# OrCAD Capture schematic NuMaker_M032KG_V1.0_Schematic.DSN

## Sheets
1 Nu-Link2-Me: size A3; title: Nu-Link2-Me; rev: 1.0; company: CMHuang; note: Nu-Link2-Me
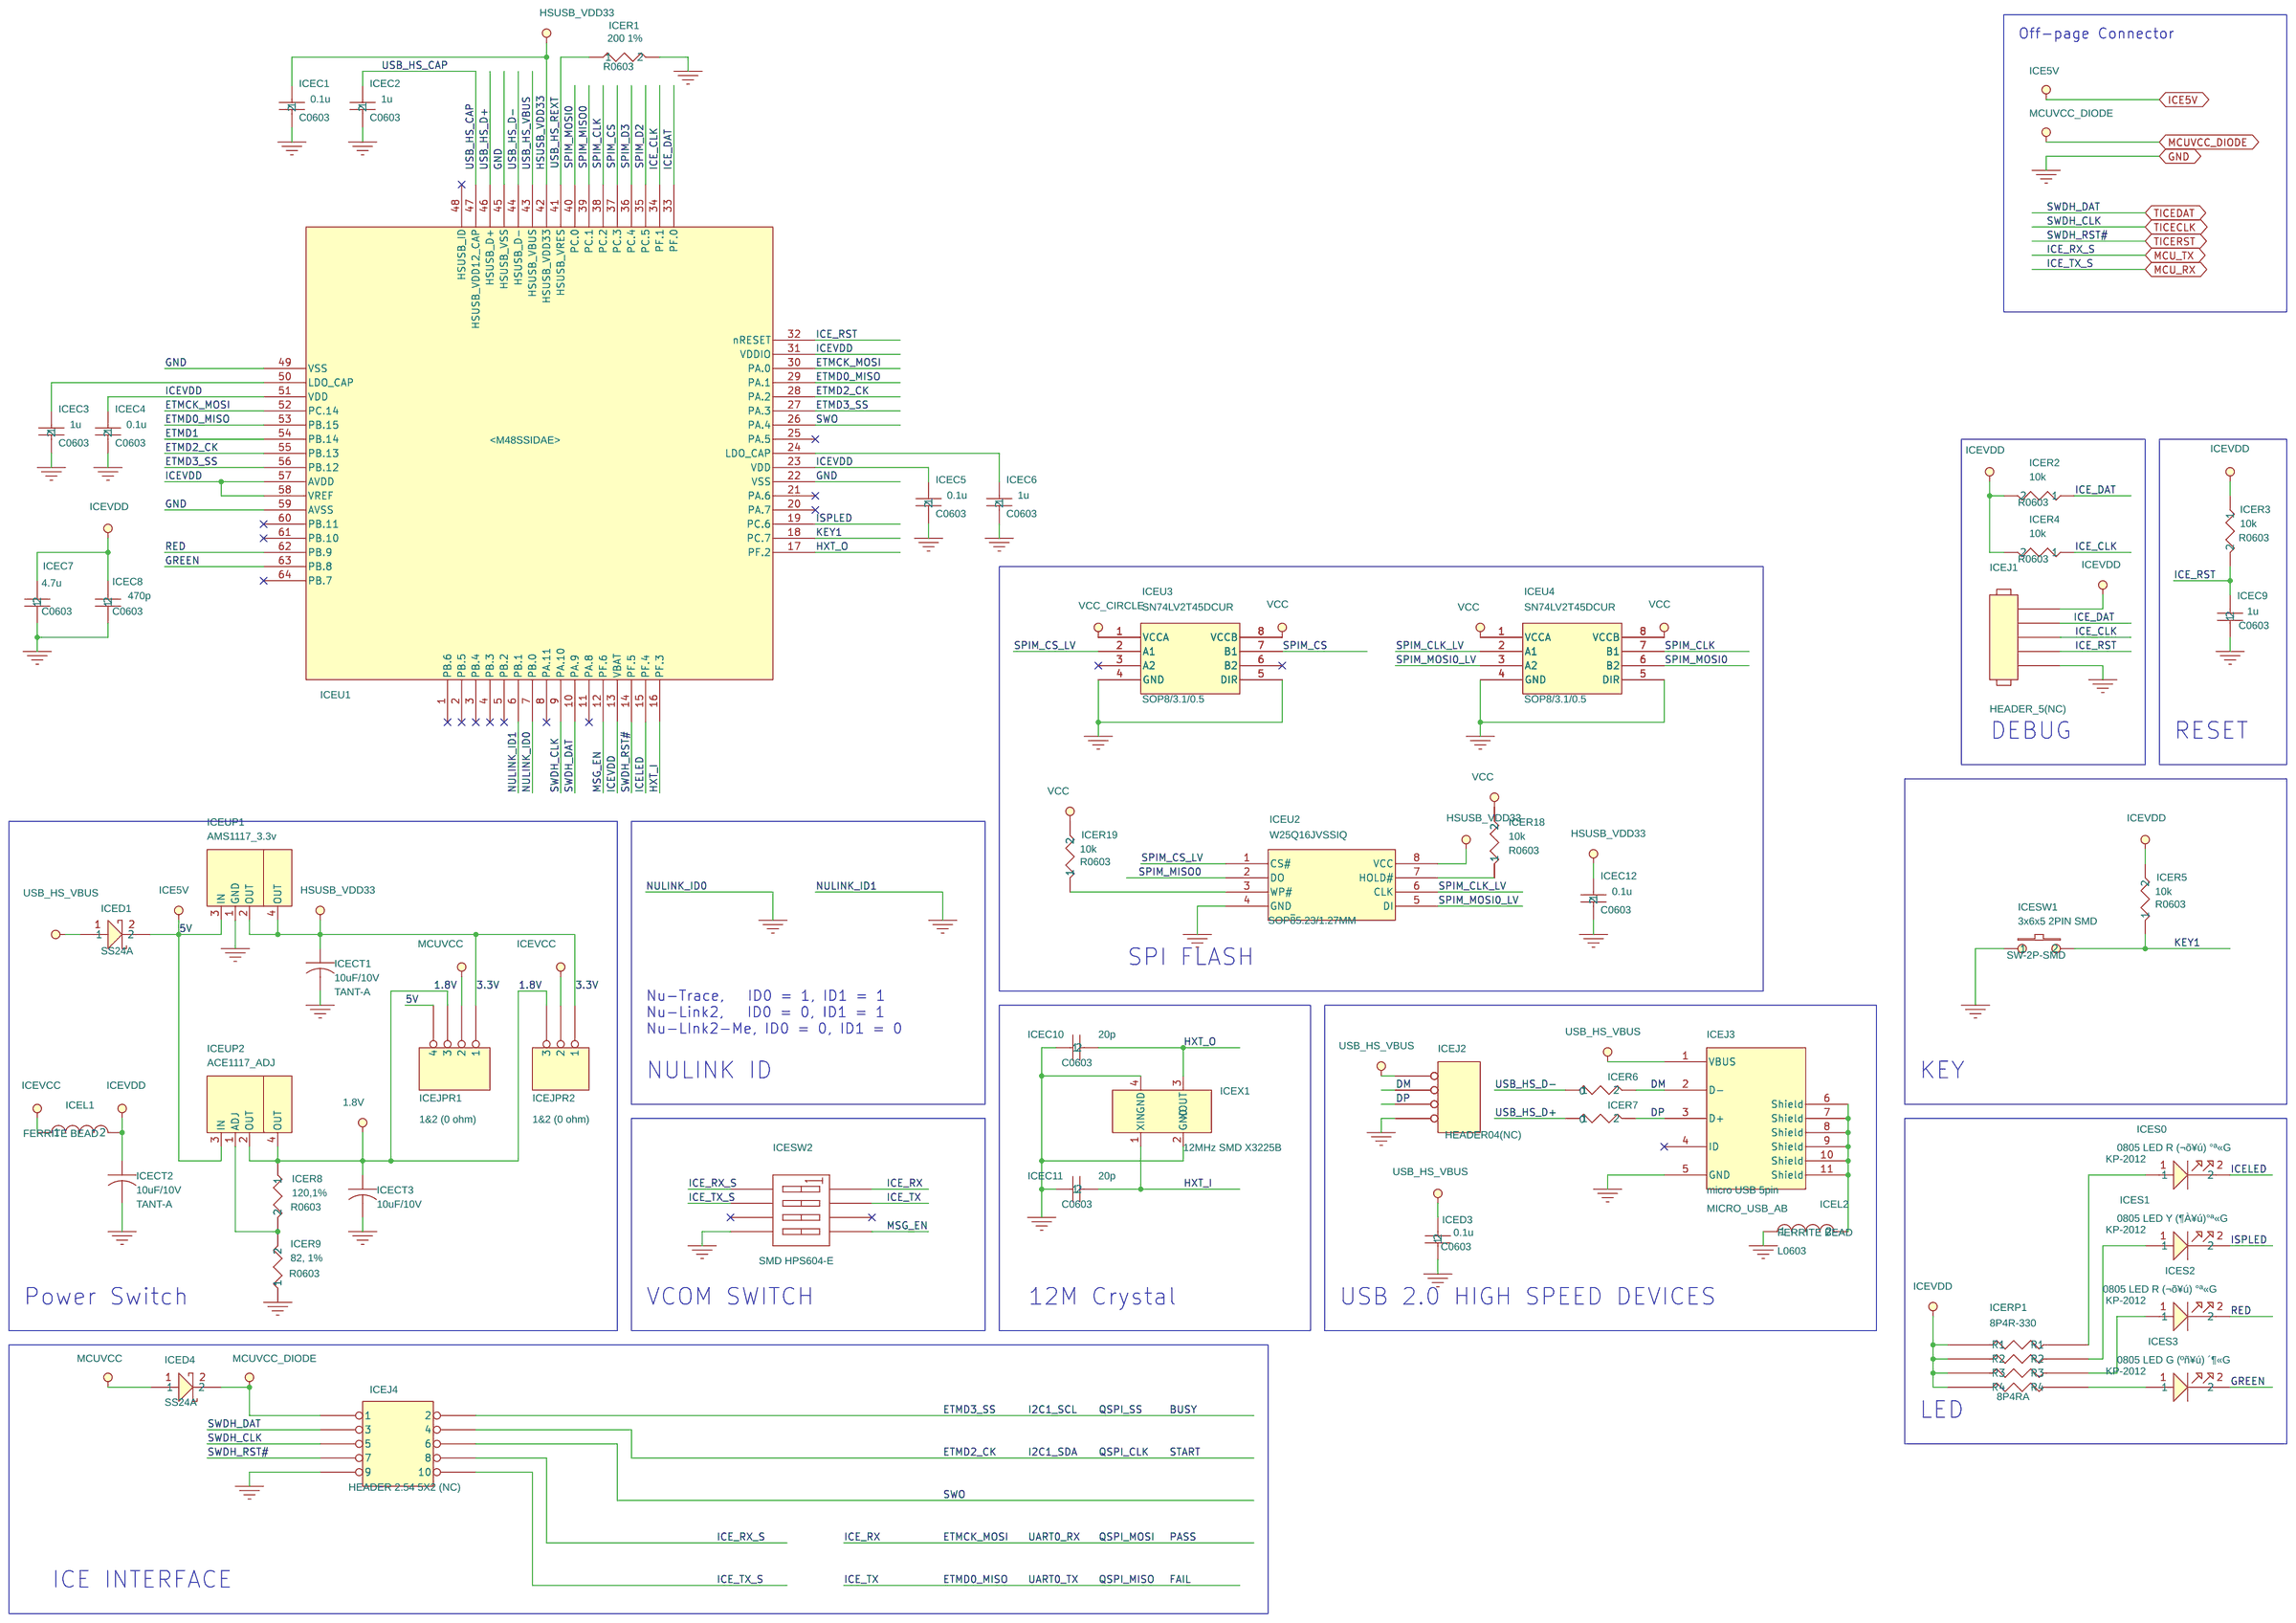
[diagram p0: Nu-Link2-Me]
2 M032KG8AE: size Custom; title: M032KG8AE; rev: v1.0; note: NuMaker-M032KG
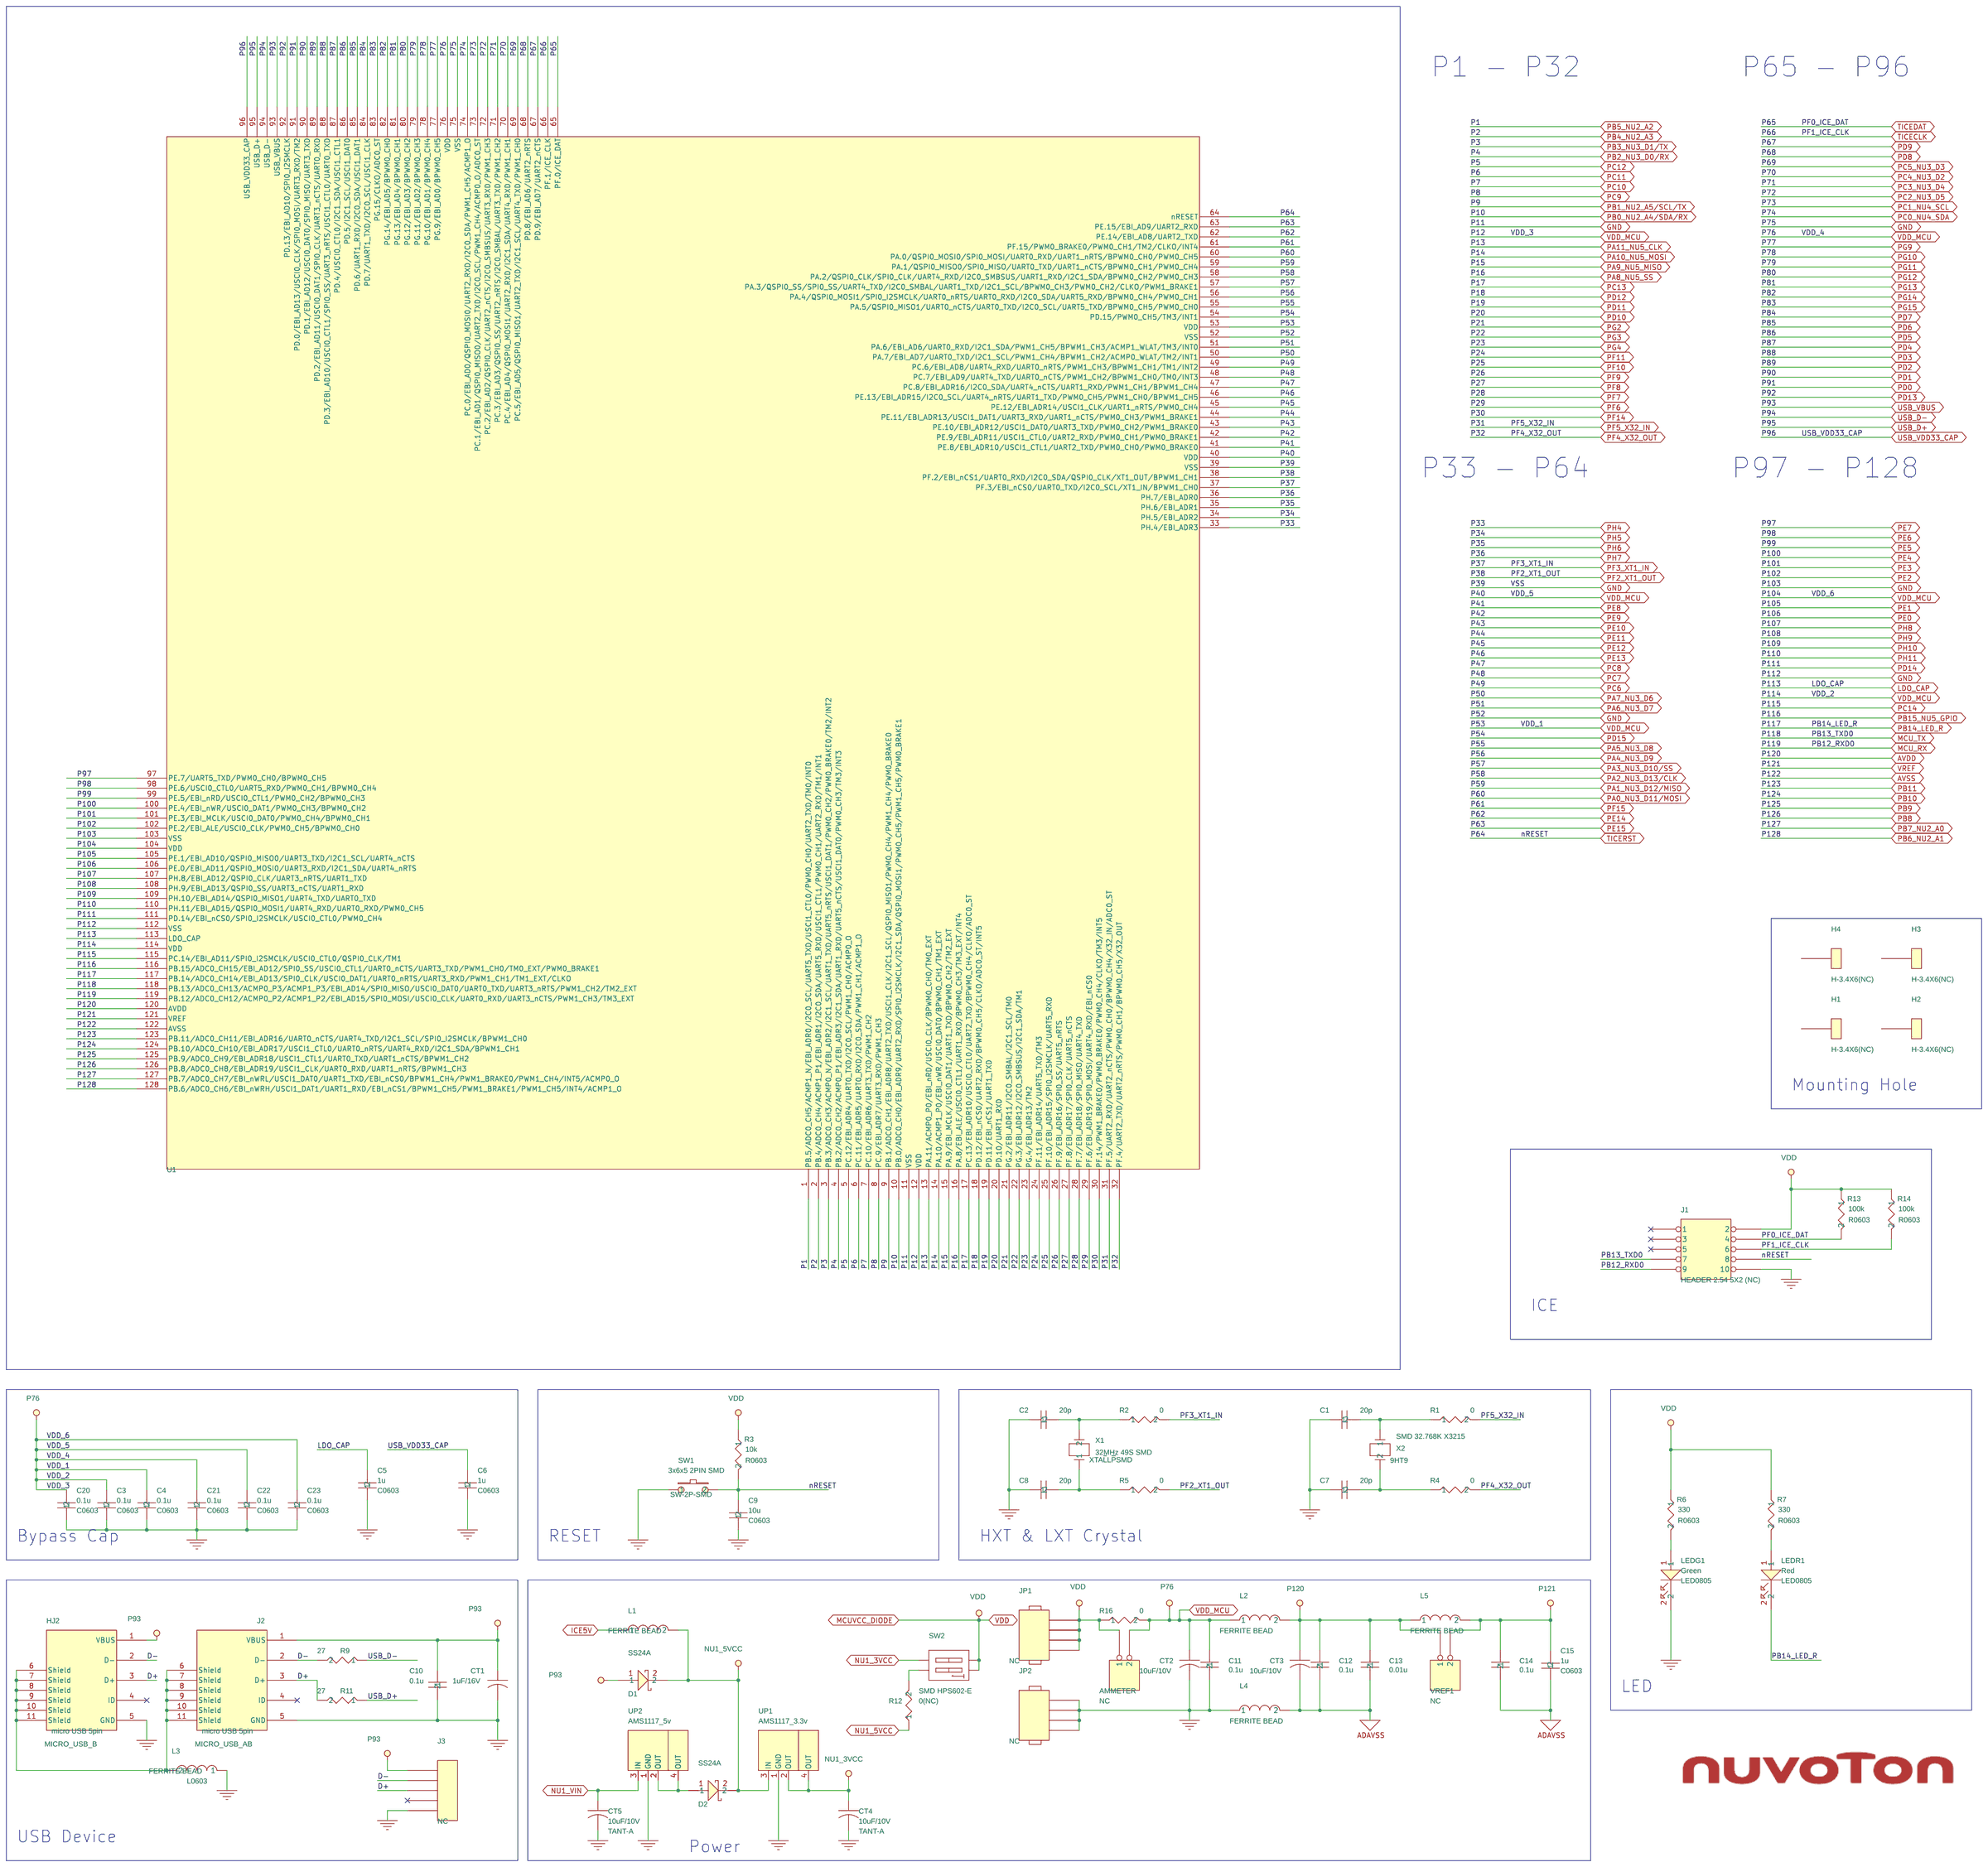
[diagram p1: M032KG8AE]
3 Ext. Connector: size Custom; title: Ext. Connector; rev: v1.0; note: NuMaker-M032KG
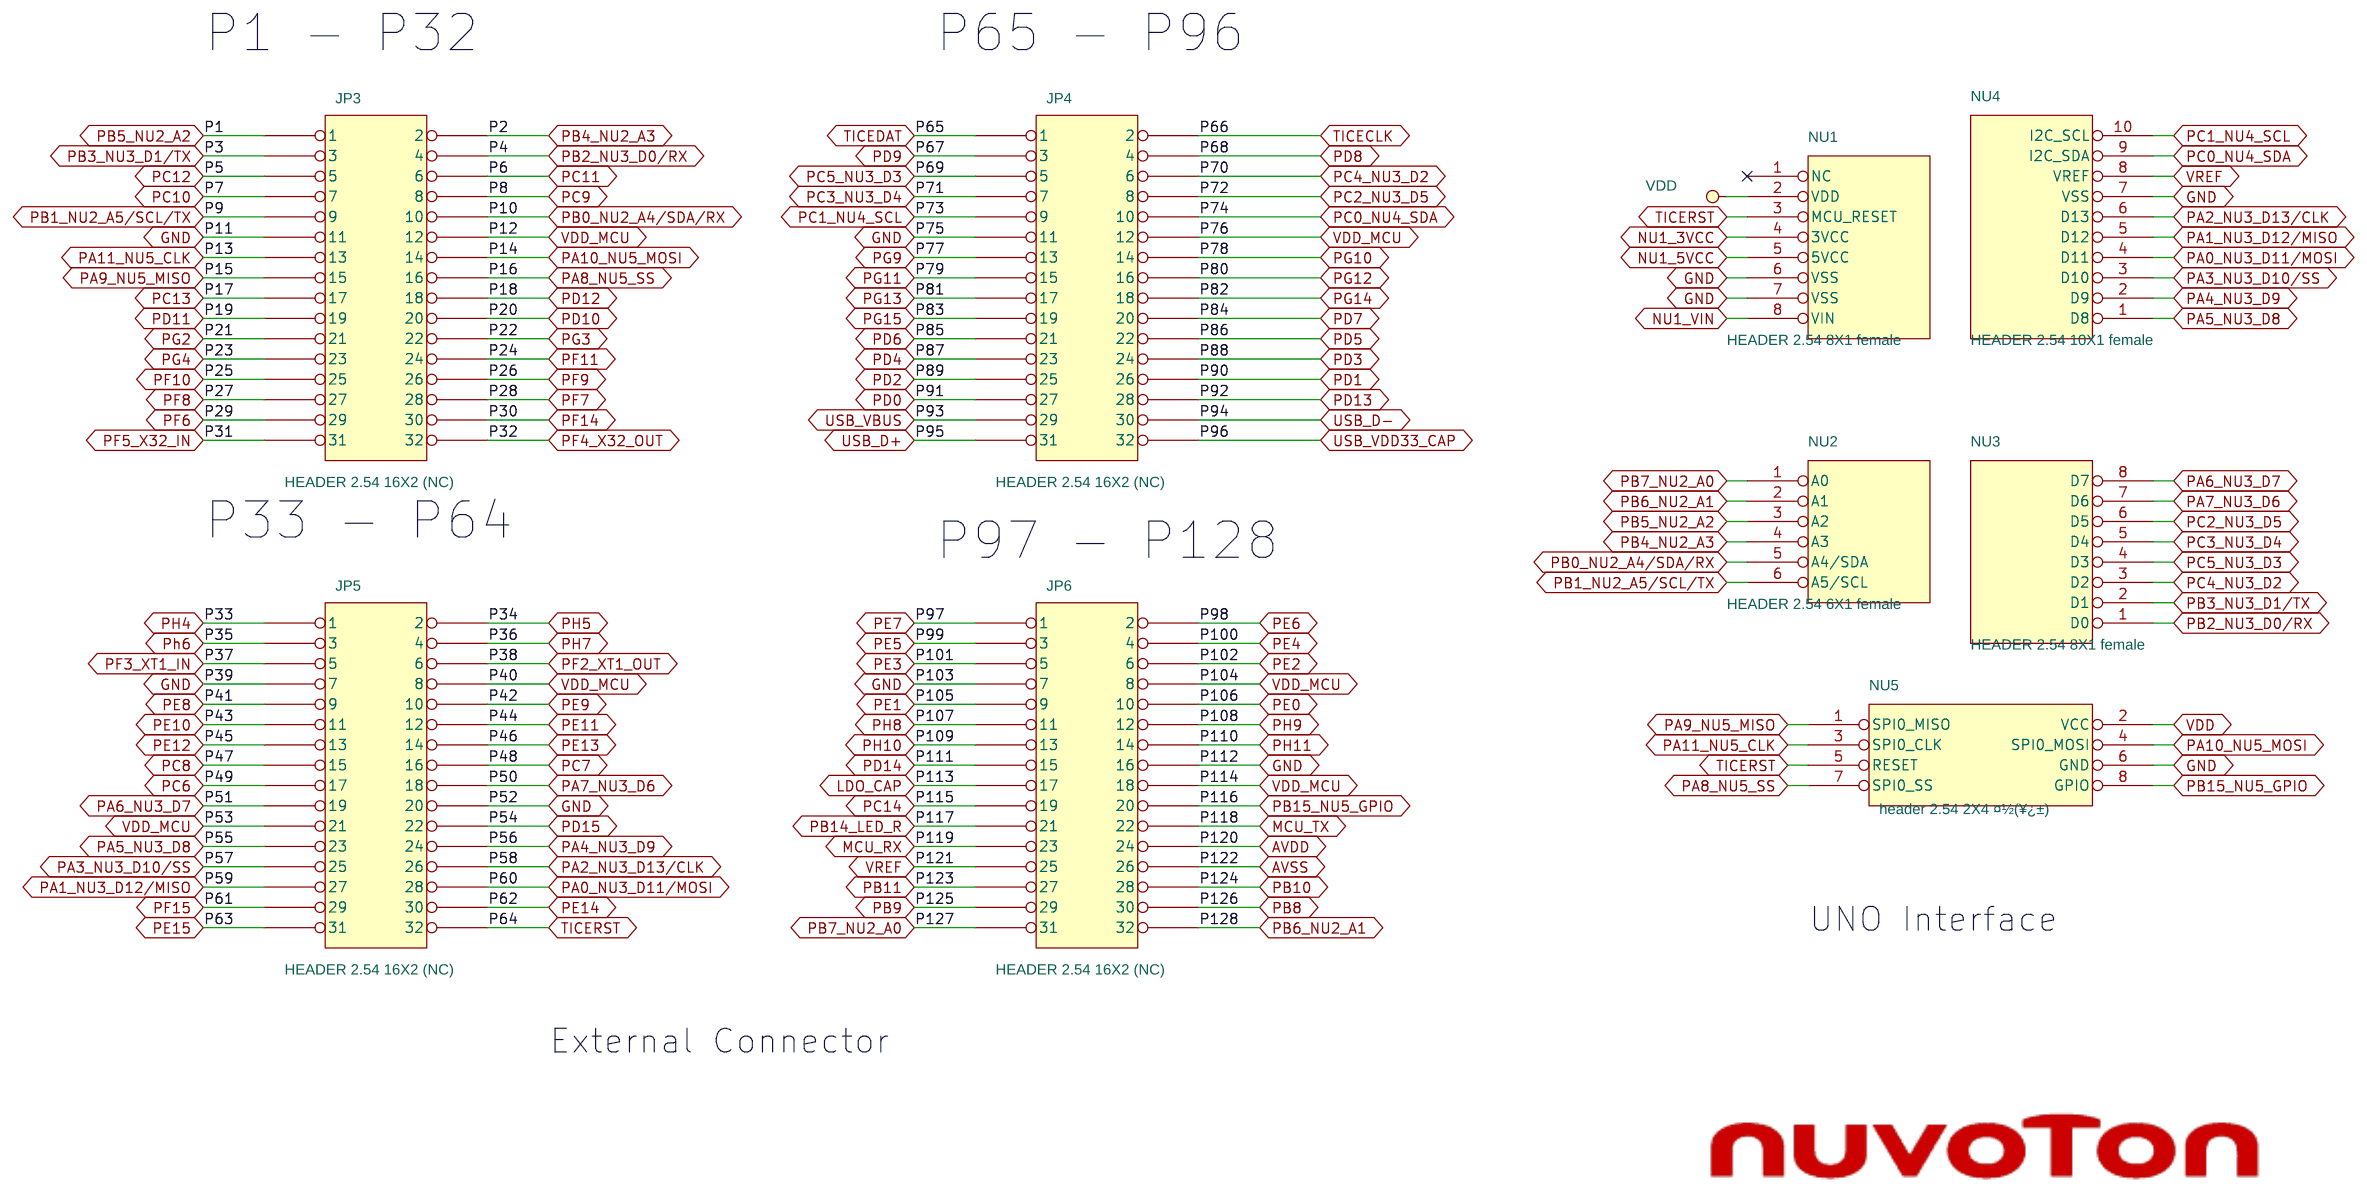
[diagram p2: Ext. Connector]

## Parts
sheet Ext. Connector
JP3  HEADER 2.54 16X2 (NC)  [HEADER16X2]
JP4  HEADER 2.54 16X2 (NC)  [HEADER16X2]
JP5  HEADER 2.54 16X2 (NC)  [HEADER16X2]
JP6  HEADER 2.54 16X2 (NC)  [HEADER16X2]
NU1  HEADER 2.54 8X1 female  [SIP-8P]
NU2  HEADER 2.54 6X1 female  [SIP-6P]
NU3  HEADER 2.54 8X1 female  [SIP-8P]
NU4  HEADER 2.54 10X1 female  [SIP-10P]
NU5  header 2.54 2X4 ¤½(¥¿­±)  [HEADER4X2]
sheet M032KG8AE
AMMETER  NC  [HEADER2X1]
C1  20p  [C0603]
C2  20p  [C0603]
C3  0.1u  [C0603]
C4  0.1u  [C0603]
C5  1u  [C0603]
C6  1u  [C0603]
C7  20p  [C0603]
C8  20p  [C0603]
C9  10u  [C0603]
C10  0.1u  [C0603]
C11  0.1u  [C0603]
C12  0.1u  [C0603]
C13  0.01u  [C0603]
C14  0.1u  [C0603]
C15  1u  [C0603]
C20  0.1u  [C0603]
C21  0.1u  [C0603]
C22  0.1u  [C0603]
C23  0.1u  [C0603]
CT1  1uF/16V  [TANT-A]
CT2  10uF/10V  [TANT-A]
CT3  10uF/10V  [TANT-A]
CT4  10uF/10V  [TANT-A]
CT5  10uF/10V  [TANT-A]
D1  SS24A  [RB060L]
D2  SS24A  [RB060L]
H1  H-3.4X6(NC)  [H-3.4X6]
H2  H-3.4X6(NC)  [H-3.4X6]
H3  H-3.4X6(NC)  [H-3.4X6]
H4  H-3.4X6(NC)  [H-3.4X6]
HJ2  micro USB 5pin  [MICRO_USB_B]
J1  HEADER 2.54 5X2 (NC)  [HEADER5X2]
J2  micro USB 5pin  [MICRO_USB_AB]
J3  NC  [HEADER5X1]
JP1  NC  [header1x4]
JP2  NC  [header1x4]
L1  FERRITE BEAD  [L0603]
L2  FERRITE BEAD  [L0603]
L3  FERRITE BEAD  [L0603]
L4  FERRITE BEAD  [L0603]
L5  FERRITE BEAD  [L0603]
LEDG1  Green  [LED0805]
LEDR1  Red  [LED0805]
R1  0  [R0603]
R2  0  [R0603]
R3  10k  [R0603]
R4  0  [R0603]
R5  0  [R0603]
R6  330  [R0603]
R7  330  [R0603]
R9  27  [R0603]
R11  27  [R0603]
R12  0(NC)  [R0603]
R13  100k  [R0603]
R14  100k  [R0603]
R16  0  [R0603]
SW1  3x6x5 2PIN SMD  [SW-2P-SMD]
SW2  SMD HPS602-E  [SW1X2]
U1  M032KG8AE  [MCU_LQFP_128]
UP1  AMS1117_3.3v  [SOT-223-1]
UP2  AMS1117_5v  [SOT-223-1]
VREF1  NC  [HEADER2X1]
X1  32MHz 49S SMD  [XTAL\LP\SMD]
X2  SMD 32.768K X3215  [9HT9]
sheet Nu-Link2-Me
ICEC1  0.1u  [C0603]
ICEC2  1u  [C0603]
ICEC3  1u  [C0603]
ICEC4  0.1u  [C0603]
ICEC5  0.1u  [C0603]
ICEC6  1u  [C0603]
ICEC7  4.7u  [C0603]
ICEC8  470p  [C0603]
ICEC9  1u  [C0603]
ICEC10  20p  [C0603]
ICEC11  20p  [C0603]
ICEC12  0.1u  [C0603]
ICECT1  10uF/10V  [TANT-A]
ICECT2  10uF/10V  [TANT-A]
ICECT3  10uF/10V  [TANT-A]
ICED1  SS24A  [RB060L]
ICED3  0.1u  [C0603]
ICED4  SS24A  [RB060L]
ICEJ1  HEADER_5(NC)  [HEADER5X1]
ICEJ2  HEADER04(NC)  [HEADER04]
ICEJ3  micro USB 5pin  [MICRO_USB_AB]
ICEJ4  HEADER 2.54 5X2 (NC)  [HEADER5X2]
ICEJPR1  1&2 (0 ohm)  [R0603X3]
ICEJPR2  1&2 (0 ohm)  [R0603X2]
ICEL1  FERRITE BEAD  [L0603]
ICEL2  FERRITE BEAD  [L0603]
ICER1  200 1%  [R0603]
ICER2  10k  [R0603]
ICER3  10k  [R0603]
ICER4  10k  [R0603]
ICER5  10k  [R0603]
ICER6  0  [R0603]
ICER7  0  [R0603]
ICER8  120,1%  [R0603]
ICER9  82, 1%  [R0603]
ICER18  10k  [R0603]
ICER19  10k  [R0603]
ICERP1  8P4R-330  [8P4RA]
ICES0  0805 LED R (¬õ¥ú) °ª«G  [KP-2012]
ICES1  0805 LED Y (¶À¥ú)°ª«G  [KP-2012]
ICES2  0805 LED R (¬õ¥ú) °ª«G  [KP-2012]
ICES3  0805 LED G (ºñ¥ú) ´¶«G  [KP-2012]
ICESW1  3x6x5 2PIN SMD  [SW-2P-SMD]
ICESW2  SMD HPS604-E  [SW1X4]
ICEU1  M48SSIDAE  [LQFP64_7x7_M48SSIDAE]
ICEU2  W25Q16JVSSIQ  [SOP8\5.23/1.27MM]
ICEU3  SN74LV2T45DCUR  [SOP8/3.1/0.5]
ICEU4  SN74LV2T45DCUR  [SOP8/3.1/0.5]
ICEUP1  AMS1117_3.3v  [SOT-223-1]
ICEUP2  ACE1117_ADJ  [SOT-223-1]
ICEX1  12MHz SMD X3225B  [CRYSTAL_SMD]

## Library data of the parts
JP3 = HEADER_16X2_2
JP4 = HEADER_16X2
JP5 = HEADER_16X2_3
JP6 = HEADER_16X2_1
NU1 = POWER_CONNECT_0
NU2 = ADC_CONNECT_0
NU3 = PWM0_CONNECT_0
NU4 = PWM1_CONNECT_1
NU5 = NuEdu_NU7
AMMETER = HEADER_2_1
C1 = C_20p_3
C2 = C_20p
C3 = CAP-C_7: Package: 0603; element_no: C0004
C4 ICED3 = CAP-C_1: Package: 0603; element_no: C0004
C5 = CAP-C_4: Package: 0603; element_no: C0006
C6 = CAP-C_3: Package: 0603; element_no: C0006
C7 = C_20p_1
C8 = C_20p_2
C9 = CAP-C_9: Package: 0603; element_no: C0006
C10 = C_0.1u_3: element_no: C0004
C11 = C_0.1u: element_no: C0004
C12 = C_0.1u_2: element_no: C0004
C13 = C_0.1u_4: element_no: C0003
C14 = C_0.1u_1: element_no: C0004
C15 = CAP-C_6: Package: 0603; element_no: C0006
C20 ICEC4 = CAP-C_2: Package: 0603; element_no: C0004
C21 = CAP-C: Package: 0603; element_no: C0004
C22 ICEC12 = CAP-C_8: Package: 0603; element_no: C0004
C23 = CAP-C_5: Package: 0603; element_no: C0004
CT1 = C_1uF_16V
CT2-CT5 ICECT1-ICECT3 = C_10uF_10V
D1 ICED1 = D_SS24A
D2 ICED4 = D_SS24A_1
H1-H4 = TEST_POINT
HJ2 ICEJ3 J2 = micro_USB_5pin_0
ICEJ4 J1 = HEADER_5X2
J3 = CON5
JP1 JP2 = HEADER_4
L1 = FERRITE_BEAD_4
L2 = FERRITE_BEAD_2
L3 = FERRITE_BEAD_3
ICEL2 L4 = FERRITE_BEAD_1
ICEL1 L5 = FERRITE_BEAD
LEDG1 = LED_0_1: Package: KP-2012; Vendor: Kingbright
LEDR1 = LED_0: Package: KP-2012; Vendor: Kingbright
R1 = R_0_1
R2 = R_0_4
ICER1 R3 = R_0_5: Package: 0603
R4 = R_0_10
R5 = R_0_3
ICER9 R6 = R_0_8: Package: 0603
ICER2 R7 = R_0: Package: 0603
ICER7 R9 = R_33_1
ICER6 R11 = R_33
R12 = R_0_7
ICER18 R13 = R_0_6: Package: 0603
R14 = R_0_9: Package: 0603
R16 = R_0_2
ICESW1 SW1 = SW_PUSHBUTTON_0
SW2 = SW_DIP-4_2
U1 = M032KG8AE
ICEUP1 UP1 UP2 = TO-247_Regulator_10
VREF1 = HEADER_2
X1 = Xtal_12MHz
X2 = Xtal_32.768K
ICEC1 = CAP-C_9: Package: 0603; element_no: C0004
ICEC2 = CAP-C_10: Package: 0603; element_no: C0006
ICEC3 = CAP-C_11: Package: 0603; element_no: C0006
ICEC5 = CAP-C_4: Package: 0603; element_no: C0004
ICEC6 = CAP-C_5: Package: 0603; element_no: C0006
ICEC7 = CAP-C: Package: 0603
ICEC8 = CAP-C_6: Package: 0603
ICEC9 = CAP-C_7: Package: 0603; element_no: C0006
ICEC10 = CAP-C_3: Package: 0603
ICEC11 = CAP-C_12: Package: 0603
ICEJ1 = HEADER_5_v2
ICEJ2 = HEADER_4_v2
ICEJPR1 = HEADER_3_0
ICEJPR2 = HEADER_3
ICER3 = R_0_4: Package: 0603
ICER4 = R_0_7: Package: 0603
ICER5 = R_0_2: Package: 0603
ICER8 = R_0_3: Package: 0603
ICER19 = R_0_1: Package: 0603
ICERP1 = R-PACK8_0
ICES0 = LED_0_3: Vendor: Kingbright
ICES1 = LED_0_1: Vendor: Kingbright
ICES2 = LED_0: Vendor: Kingbright
ICES3 = LED_0_2: Vendor: Kingbright
ICESW2 = SW_DIP-4_SM
ICEU1 = M487SIDAE_0: M487SIDAE: <M48SSIDAE>
ICEU2 = W25P10_20_40_SOIC_0: Package: SOP8; Vendor: WINBOND
ICEU3 ICEU4 = SN74LV2T45
ICEUP2 = TO-247_Regulator_0
ICEX1 = Crystal_SMD_1

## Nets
1.8V: ICECT3.1 ICEJPR1.3 ICEJPR2.3 ICER8.1 ICEUP2.2(OUT) ICEUP2.4(OUT)
3.3V: ICEC1.1 ICEC12.1 ICECT1.1 ICEJPR1.1 ICEJPR2.1 ICER18.2 ICER19.2 ICEU1.42(HSUSB_VDD33) ICEU2.8(VCC) ICEU3.1(VCCA) ICEU4.1(VCCA) ICEUP1.2(OUT) ICEUP1.4(OUT)
AVDD: C12.1 C13.1 CT3.1 JP6.24 L2.2 L5.1 U1.120(AVDD) VREF1.1
AVSS: C12.2 C13.2 C14.2 C15.1 CT3.2 JP6.26 L4.2 U1.122(AVSS)
GND: C1.1 C2.1 C3.1 C4.1 C5.1 C6.1 C7.1 C8.1 C9.1 C10.2 C11.2 C20.1 C21.1 C22.1 C23.1 CT1.2 CT2.2 CT4.2 CT5.2 HJ2.5(GND) ICEC1.2 ICEC2.2 ICEC3.2 ICEC4.2 ICEC5.2 ICEC6.2 ICEC7.1 ICEC8.1 ICEC9.1 ICEC10.1 ICEC11.1 ICEC12.2 ICECT1.2 ICECT2.2 ICECT3.2 ICED3.1 ICEJ1.5 ICEJ2.4 ICEJ3.5(GND) ICEJ4.9 ICEL2.1 ICER1.2 ICER9.1 ICESW1.1 ICESW2.4(A4) ICEU1.6(PB.1) ICEU1.7(PB.0) ICEU1.22(VSS) ICEU1.45(HSUSB_VSS) ICEU1.49(VSS) ICEU1.59(AVSS) ICEU2.4(GND) ICEU3.4(GND) ICEU3.5(DIR) ICEU4.4(GND) ICEU4.5(DIR) ICEUP1.1(GND) ICEX1.2(GND) ICEX1.4(GND) J1.10 J2.5(GND) J3.5 JP2.1 JP2.2 JP2.3 JP2.4 JP3.11 JP4.11 JP5.7 JP5.20 JP6.7 JP6.16 L3.1 L4.1 LEDG1.2 NU1.6(VSS) NU1.7(VSS) NU4.7(VSS) NU5.6(GND) SW1.1 U1.11(VSS) U1.39(VSS) U1.52(VSS) U1.75(VSS) U1.103(VSS) U1.112(VSS) UP1.1(GND) UP2.1(GND)
VDD: AMMETER.1 ICED4.2 ICEJ4.1 J1.2 JP1.1 JP1.2 JP1.3 JP1.4 NU1.2(VDD) NU5.2(VCC) R3.1 R6.1 R7.1 R13.1 R14.1 R16.1 SW2.3(B1) SW2.4(B2)
VDD_MCU: AMMETER.2 C3.2 C4.2 C11.1 C20.2 C21.2 C22.2 C23.2 CT2.1 JP3.12 JP4.12 JP5.8 JP5.21 JP6.8 JP6.18 L2.1 R16.2 U1.12(VDD) U1.40(VDD) U1.53(VDD) U1.76(VDD) U1.104(VDD) U1.114(VDD)
BUSY: ICEJ4.2 ICEU1.27(PA.3) ICEU1.56(PB.12)
D+: HJ2.3(D+) J2.3(D+) J3.3 R11.2
D-: HJ2.2(D-) J2.2(D-) J3.2 R9.2
DM: ICEJ2.2 ICEJ3.2(D-) ICER6.2
DP: ICEJ2.3 ICEJ3.3(D+) ICER7.2
ETMD1: ICEU1.54(PB.14)
ETMD2_CK: ICEJ4.4 ICEU1.28(PA.2) ICEU1.55(PB.13)
GREEN: ICES3.2 ICEU1.63(PB.8)
HXT_I: ICEC11.2 ICEU1.16(PF.3) ICEX1.1(XIN)
HXT_O: ICEC10.2 ICEU1.17(PF.2) ICEX1.3(XOUT)
ICE5V: ICED1.2 ICEJPR1.4 ICEUP1.3(IN) ICEUP2.3(IN) L1.1
ICE_CLK: ICEJ1.3 ICER4.1 ICEU1.34(PF.1)
ICE_DAT: ICEJ1.2 ICER2.1 ICEU1.33(PF.0)
ICE_RST: ICEC9.2 ICEJ1.4 ICER3.2 ICEU1.32(nRESET)
ICE_RX: ICESW2.8(B1) ICEU1.30(PA.0) ICEU1.52(PC.14)
ICE_TX: ICESW2.7(B2) ICEU1.29(PA.1) ICEU1.53(PB.15)
ICELED: ICES0.2 ICEU1.15(PF.4)
ICEVCC: ICEJPR2.2 ICEL1.1
ICEVDD: ICEC4.1 ICEC5.1 ICEC7.2 ICEC8.2 ICECT2.1 ICEJ1.1 ICEL1.2 ICER2.2 ICER3.1 ICER4.2 ICER5.2 ICERP1.1(R1) ICERP1.3(R2) ICERP1.5(R3) ICERP1.7(R4) ICEU1.13(VBAT) ICEU1.23(VDD) ICEU1.31(VDDIO) ICEU1.51(VDD) ICEU1.57(AVDD) ICEU1.58(VREF) ICEU3.8(VCCB) ICEU4.8(VCCB)
ISPLED: ICES1.2 ICEU1.19(PC.6)
KEY1: ICER5.1 ICESW1.2 ICEU1.18(PC.7)
LDO_CAP: C5.2 JP6.17 U1.113(LDO_CAP)
MCU_RX: ICEJ4.10 ICESW2.2(A2) J1.9 JP6.23 U1.119(PB.12/ADC0_CH12/ACMP0_P2/ACMP1_P2/EBI_AD15/SPI0_MOSI/USCI0_CLK/UART0_RXD/UART3_nCTS/PWM1_CH3/TM3_EXT)
MCU_TX: ICEJ4.8 ICESW2.1(A1) J1.7 JP6.22 U1.118(PB.13/ADC0_CH13/ACMP0_P3/ACMP1_P3/EBI_AD14/SPI0_MISO/USCI0_DAT0/UART0_TXD/UART3_nRTS/PWM1_CH2/TM2_EXT)
MCUVCC: ICED4.1 ICEJPR1.2
MSG_EN: ICESW2.5(B4) ICEU1.12(PF.6)
NU1_3VCC: CT4.1 NU1.4(3VCC) SW2.2(A2) UP1.2(OUT) UP1.4(OUT)
NU1_5VCC: D1.2 D2.2 L1.2 NU1.5(5VCC) R12.1 UP1.3(IN)
NU1_VIN: CT5.1 NU1.8(VIN) UP2.3(IN)
PA0_NU3_D11/MOSI: JP5.28 NU4.4(D11) U1.60(PA.0/QSPI0_MOSI0/SPI0_MOSI/UART0_RXD/UART1_nRTS/BPWM0_CH0/PWM0_CH5)
PA1_NU3_D12/MISO: JP5.27 NU4.5(D12) U1.59(PA.1/QSPI0_MISO0/SPI0_MISO/UART0_TXD/UART1_nCTS/BPWM0_CH1/PWM0_CH4)
PA2_NU3_D13/CLK: JP5.26 NU4.6(D13) U1.58(PA.2/QSPI0_CLK/SPI0_CLK/UART4_RXD/I2C0_SMBSUS/UART1_RXD/I2C1_SDA/BPWM0_CH2/PWM0_CH3)
PA3_NU3_D10/SS: JP5.25 NU4.3(D10) U1.57(PA.3/QSPI0_SS/SPI0_SS/UART4_TXD/I2C0_SMBAL/UART1_TXD/I2C1_SCL/BPWM0_CH3/PWM0_CH2/CLKO/PWM1_BRAKE1)
PA4_NU3_D9: JP5.24 NU4.2(D9) U1.56(PA.4/QSPI0_MOSI1/SPI0_I2SMCLK/UART0_nRTS/UART0_RXD/I2C0_SDA/UART5_RXD/BPWM0_CH4/PWM0_CH1)
PA5_NU3_D8: JP5.23 NU4.1(D8) U1.55(PA.5/QSPI0_MISO1/UART0_nCTS/UART0_TXD/I2C0_SCL/UART5_TXD/BPWM0_CH5/PWM0_CH0)
PA6_NU3_D7: JP5.19 NU3.8(D7) U1.51(PA.6/EBI_AD6/UART0_RXD/I2C1_SDA/PWM1_CH5/BPWM1_CH3/ACMP1_WLAT/TM3/INT0)
PA7_NU3_D6: JP5.18 NU3.7(D6) U1.50(PA.7/EBI_AD7/UART0_TXD/I2C1_SCL/PWM1_CH4/BPWM1_CH2/ACMP0_WLAT/TM2/INT1)
PA8_NU5_SS: JP3.16 NU5.7(SPI0_SS) U1.16(PA.8/EBI_ALE/USCI0_CTL1/UART1_RXD/BPWM0_CH3/TM3_EXT/INT4)
PA9_NU5_MISO: JP3.15 NU5.1(SPI0_MISO) U1.15(PA.9/EBI_MCLK/USCI0_DAT1/UART1_TXD/BPWM0_CH2/TM2_EXT)
PA10_NU5_MOSI: JP3.14 NU5.4(SPI0_MOSI) U1.14(PA.10/ACMP1_P0/EBI_nWR/USCI0_DAT0/BPWM0_CH1/TM1_EXT)
PA11_NU5_CLK: JP3.13 NU5.3(SPI0_CLK) U1.13(PA.11/ACMP0_P0/EBI_nRD/USCI0_CLK/BPWM0_CH0/TM0_EXT)
PB0_NU2_A4/SDA/RX: JP3.10 NU2.5(A4/SDA) U1.10(PB.0/ADC0_CH0/EBI_ADR9/UART2_RXD/SPI0_I2SMCLK/I2C1_SDA/QSPI0_MOSI1/PWM0_CH5/PWM1_CH5/PWM0_BRAKE1)
PB1_NU2_A5/SCL/TX: JP3.9 NU2.6(A5/SCL) U1.9(PB.1/ADC0_CH1/EBI_ADR8/UART2_TXD/USCI1_CLK/I2C1_SCL/QSPI0_MISO1/PWM0_CH4/PWM1_CH4/PWM0_BRAKE0)
PB2_NU3_D0/RX: JP3.4 NU3.1(D0) U1.4(PB.2/ADC0_CH2/ACMP0_P1/EBI_ADR3/I2C1_SDA/UART1_RXD/UART5_nCTS/USCI1_DAT0/PWM0_CH3/TM3/INT3)
PB3_NU3_D1/TX: JP3.3 NU3.2(D1) U1.3(PB.3/ADC0_CH3/ACMP0_N/EBI_ADR2/I2C1_SCL/UART1_TXD/UART5_nRTS/USCI1_DAT1/PWM0_CH2/PWM0_BRAKE0/TM2/INT2)
PB4_NU2_A3: JP3.2 NU2.4(A3) U1.2(PB.4/ADC0_CH4/ACMP1_P1/EBI_ADR1/I2C0_SDA/UART5_RXD/USCI1_CTL1/PWM0_CH1/UART2_RXD/TM1/INT1)
PB5_NU2_A2: JP3.1 NU2.3(A2) U1.1(PB.5/ADC0_CH5/ACMP1_N/EBI_ADR0/I2C0_SCL/UART5_TXD/USCI1_CTL0/PWM0_CH0/UART2_TXD/TM0/INT0)
PB6_NU2_A1: JP6.32 NU2.2(A1) U1.128(PB.6/ADC0_CH6/EBI_nWRH/USCI1_DAT1/UART1_RXD/EBI_nCS1/BPWM1_CH5/PWM1_BRAKE1/PWM1_CH5/INT4/ACMP1_O)
PB7_NU2_A0: JP6.31 NU2.1(A0) U1.127(PB.7/ADC0_CH7/EBI_nWRL/USCI1_DAT0/UART1_TXD/EBI_nCS0/BPWM1_CH4/PWM1_BRAKE0/PWM1_CH4/INT5/ACMP0_O)
PB8: JP6.30 U1.126(PB.8/ADC0_CH8/EBI_ADR19/USCI1_CLK/UART0_RXD/UART1_nRTS/BPWM1_CH3)
PB9: JP6.29 U1.125(PB.9/ADC0_CH9/EBI_ADR18/USCI1_CTL1/UART0_TXD/UART1_nCTS/BPWM1_CH2)
PB10: JP6.28 U1.124(PB.10/ADC0_CH10/EBI_ADR17/USCI1_CTL0/UART0_nRTS/UART4_RXD/I2C1_SDA/BPWM1_CH1)
PB11: JP6.27 U1.123(PB.11/ADC0_CH11/EBI_ADR16/UART0_nCTS/UART4_TXD/I2C1_SCL/SPI0_I2SMCLK/BPWM1_CH0)
PB14_LED_R: JP6.21 LEDR1.2 U1.117(PB.14/ADC0_CH14/EBI_AD13/SPI0_CLK/USCI0_DAT1/UART0_nRTS/UART3_RXD/PWM1_CH1/TM1_EXT/CLKO)
PB15_NU5_GPIO: JP6.20 NU5.8(GPIO) U1.116(PB.15/ADC0_CH15/EBI_AD12/SPI0_SS/USCI0_CTL1/UART0_nCTS/UART3_TXD/PWM1_CH0/TM0_EXT/PWM0_BRAKE1)
PC0_NU4_SDA: JP4.10 NU4.9(I2C_SDA) U1.74(PC.0/EBI_AD0/QSPI0_MOSI0/UART2_RXD/I2C0_SDA/PWM1_CH5/ACMP1_O)
PC1_NU4_SCL: JP4.9 NU4.10(I2C_SCL) U1.73(PC.1/EBI_AD1/QSPI0_MISO0/UART2_TXD/I2C0_SCL/PWM1_CH4/ACMP0_O/ADC0_ST)
PC2_NU3_D5: JP4.8 NU3.6(D5) U1.72(PC.2/EBI_AD2/QSPI0_CLK/UART2_nCTS/I2C0_SMBSUS/UART3_RXD/PWM1_CH3)
PC3_NU3_D4: JP4.7 NU3.5(D4) U1.71(PC.3/EBI_AD3/QSPI0_SS/UART2_nRTS/I2C0_SMBAL/UART3_TXD/PWM1_CH2)
PC4_NU3_D2: JP4.6 NU3.3(D2) U1.70(PC.4/EBI_AD4/QSPI0_MOSI1/UART2_RXD/I2C1_SDA/UART4_RXD/PWM1_CH1)
PC5_NU3_D3: JP4.5 NU3.4(D3) U1.69(PC.5/EBI_AD5/QSPI0_MISO1/UART2_TXD/I2C1_SCL/UART4_TXD/PWM1_CH0)
PC6: JP5.17 U1.49(PC.6/EBI_AD8/UART4_RXD/UART0_nRTS/PWM1_CH3/BPWM1_CH1/TM1/INT2)
PC7: JP5.16 U1.48(PC.7/EBI_AD9/UART4_TXD/UART0_nCTS/PWM1_CH2/BPWM1_CH0/TM0/INT3)
PC8: JP5.15 U1.47(PC.8/EBI_ADR16/I2C0_SDA/UART4_nCTS/UART1_RXD/PWM1_CH1/BPWM1_CH4)
PC9: JP3.8 U1.8(PC.9/EBI_ADR7/UART3_RXD/PWM1_CH3)
PC10: JP3.7 U1.7(PC.10/EBI_ADR6/UART3_TXD/PWM1_CH2)
PC11: JP3.6 U1.6(PC.11/EBI_ADR5/UART0_RXD/I2C0_SDA/PWM1_CH1/ACMP1_O)
PC12: JP3.5 U1.5(PC.12/EBI_ADR4/UART0_TXD/I2C0_SCL/PWM1_CH0/ACMP0_O)
PC13: JP3.17 U1.17(PC.13/EBI_ADR10/USCI0_CTL0/UART2_TXD/BPWM0_CH4/CLKO/ADC0_ST)
PC14: JP6.19 U1.115(PC.14/EBI_AD11/SPI0_I2SMCLK/USCI0_CTL0/QSPI0_CLK/TM1)
PD0: JP4.27 U1.91(PD.0/EBI_AD13/USCI0_CLK/SPI0_MOSI/UART3_RXD/TM2)
PD1: JP4.26 U1.90(PD.1/EBI_AD12/USCI0_DAT0/SPI0_MISO/UART3_TXD)
PD2: JP4.25 U1.89(PD.2/EBI_AD11/USCI0_DAT1/SPI0_CLK/UART3_nCTS/UART0_RXD)
PD3: JP4.24 U1.88(PD.3/EBI_AD10/USCI0_CTL1/SPI0_SS/UART3_nRTS/USCI1_CTL0/UART0_TXD)
PD4: JP4.23 U1.87(PD.4/USCI0_CTL0/I2C1_SDA/USCI1_CTL1)
PD5: JP4.22 U1.86(PD.5/I2C1_SCL/USCI1_DAT0)
PD6: JP4.21 U1.85(PD.6/UART1_RXD/I2C0_SDA/USCI1_DAT1)
PD7: JP4.20 U1.84(PD.7/UART1_TXD/I2C0_SCL/USCI1_CLK)
PD8: JP4.4 U1.68(PD.8/EBI_AD6/UART2_nRTS)
PD9: JP4.3 U1.67(PD.9/EBI_AD7/UART2_nCTS)
PD10: JP3.20 U1.20(PD.10/UART1_RXD)
PD11: JP3.19 U1.19(PD.11/EBI_nCS1/UART1_TXD)
PD12: JP3.18 U1.18(PD.12/EBI_nCS0/UART2_RXD/BPWM0_CH5/CLKO/ADC0_ST/INT5)
PD13: JP4.28 U1.92(PD.13/EBI_AD10/SPI0_I2SMCLK)
PD14: JP6.15 U1.111(PD.14/EBI_nCS0/SPI0_I2SMCLK/USCI0_CTL0/PWM0_CH4)
PD15: JP5.22 U1.54(PD.15/PWM0_CH5/TM3/INT1)
PE0: JP6.10 U1.106(PE.0/EBI_AD11/QSPI0_MOSI0/UART3_RXD/I2C1_SDA/UART4_nRTS)
PE1: JP6.9 U1.105(PE.1/EBI_AD10/QSPI0_MISO0/UART3_TXD/I2C1_SCL/UART4_nCTS)
PE2: JP6.6 U1.102(PE.2/EBI_ALE/USCI0_CLK/PWM0_CH5/BPWM0_CH0)
PE3: JP6.5 U1.101(PE.3/EBI_MCLK/USCI0_DAT0/PWM0_CH4/BPWM0_CH1)
PE4: JP6.4 U1.100(PE.4/EBI_nWR/USCI0_DAT1/PWM0_CH3/BPWM0_CH2)
PE5: JP6.3 U1.99(PE.5/EBI_nRD/USCI0_CTL1/PWM0_CH2/BPWM0_CH3)
PE6: JP6.2 U1.98(PE.6/USCI0_CTL0/UART5_RXD/PWM0_CH1/BPWM0_CH4)
PE7: JP6.1 U1.97(PE.7/UART5_TXD/PWM0_CH0/BPWM0_CH5)
PE8: JP5.9 U1.41(PE.8/EBI_ADR10/USCI1_CTL1/UART2_TXD/PWM0_CH0/PWM0_BRAKE0)
PE9: JP5.10 U1.42(PE.9/EBI_ADR11/USCI1_CTL0/UART2_RXD/PWM0_CH1/PWM0_BRAKE1)
PE10: JP5.11 U1.43(PE.10/EBI_ADR12/USCI1_DAT0/UART3_TXD/PWM0_CH2/PWM1_BRAKE0)
PE11: JP5.12 U1.44(PE.11/EBI_ADR13/USCI1_DAT1/UART3_RXD/UART1_nCTS/PWM0_CH3/PWM1_BRAKE1)
PE12: JP5.13 U1.45(PE.12/EBI_ADR14/USCI1_CLK/UART1_nRTS/PWM0_CH4)
PE13: JP5.14 U1.46(PE.13/EBI_ADR15/I2C0_SCL/UART4_nRTS/UART1_TXD/PWM0_CH5/PWM1_CH0/BPWM1_CH5)
PE14: JP5.30 U1.62(PE.14/EBI_AD8/UART2_TXD)
PE15: JP5.31 U1.63(PE.15/EBI_AD9/UART2_RXD)
PF2_XT1_OUT: JP5.6 R5.2 U1.38(PF.2/EBI_nCS1/UART0_RXD/I2C0_SDA/QSPI0_CLK/XT1_OUT/BPWM1_CH1)
PF3_XT1_IN: JP5.5 R2.2 U1.37(PF.3/EBI_nCS0/UART0_TXD/I2C0_SCL/XT1_IN/BPWM1_CH0)
PF4_X32_OUT: JP3.32 R4.2 U1.32(PF.4/UART2_TXD/UART2_nRTS/PWM0_CH1/BPWM0_CH5/X32_OUT)
PF5_X32_IN: JP3.31 R1.2 U1.31(PF.5/UART2_RXD/UART2_nCTS/PWM0_CH0/BPWM0_CH4/X32_IN/ADC0_ST)
PF6: JP3.29 U1.29(PF.6/EBI_ADR19/SPI0_MOSI/UART4_RXD/EBI_nCS0)
PF7: JP3.28 U1.28(PF.7/EBI_ADR18/SPI0_MISO/UART4_TXD)
PF8: JP3.27 U1.27(PF.8/EBI_ADR17/SPI0_CLK/UART5_nCTS)
PF9: JP3.26 U1.26(PF.9/EBI_ADR16/SPI0_SS/UART5_nRTS)
PF10: JP3.25 U1.25(PF.10/EBI_ADR15/SPI0_I2SMCLK/UART5_RXD)
PF11: JP3.24 U1.24(PF.11/EBI_ADR14/UART5_TXD/TM3)
PF14: JP3.30 U1.30(PF.14/PWM1_BRAKE0/PWM0_BRAKE0/PWM0_CH4/CLKO/TM3/INT5)
PF15: JP5.29 U1.61(PF.15/PWM0_BRAKE0/PWM0_CH1/TM2/CLKO/INT4)
PG2: JP3.21 U1.21(PG.2/EBI_ADR11/I2C0_SMBAL/I2C1_SCL/TM0)
PG3: JP3.22 U1.22(PG.3/EBI_ADR12/I2C0_SMBSUS/I2C1_SDA/TM1)
PG4: JP3.23 U1.23(PG.4/EBI_ADR13/TM2)
PG9: JP4.13 U1.77(PG.9/EBI_AD0/BPWM0_CH5)
PG10: JP4.14 U1.78(PG.10/EBI_AD1/BPWM0_CH4)
PG11: JP4.15 U1.79(PG.11/EBI_AD2/BPWM0_CH3)
PG12: JP4.16 U1.80(PG.12/EBI_AD3/BPWM0_CH2)
PG13: JP4.17 U1.81(PG.13/EBI_AD4/BPWM0_CH1)
PG14: JP4.18 U1.82(PG.14/EBI_AD5/BPWM0_CH0)
PG15: JP4.19 U1.83(PG.15/CLKO/ADC0_ST)
PH4: JP5.1 U1.33(PH.4/EBI_ADR3)
PH5: JP5.2 U1.34(PH.5/EBI_ADR2)
PH6: JP5.3 U1.35(PH.6/EBI_ADR1)
PH7: JP5.4 U1.36(PH.7/EBI_ADR0)
PH8: JP6.11 U1.107(PH.8/EBI_AD12/QSPI0_CLK/UART3_nRTS/UART1_TXD)
PH9: JP6.12 U1.108(PH.9/EBI_AD13/QSPI0_SS/UART3_nCTS/UART1_RXD)
PH10: JP6.13 U1.109(PH.10/EBI_AD14/QSPI0_MISO1/UART4_TXD/UART0_TXD)
PH11: JP6.14 U1.110(PH.11/EBI_AD15/QSPI0_MOSI1/UART4_RXD/UART0_RXD/PWM0_CH5)
RED: ICES2.2 ICEU1.62(PB.9)
SPIM_CLK: ICEU1.38(PC.2) ICEU4.7(B1)
SPIM_CLK_LV: ICEU2.6(CLK) ICEU4.2(A1)
SPIM_CS: ICEU1.37(PC.3) ICEU3.7(B1)
SPIM_CS_LV: ICEU2.1(CS#) ICEU3.2(A1)
SPIM_D2: ICEU1.35(PC.5)
SPIM_D3: ICEU1.36(PC.4)
SPIM_MISO0: ICEU1.39(PC.1) ICEU2.2(DO)
SPIM_MOSI0: ICEU1.40(PC.0) ICEU4.6(B2)
SPIM_MOSI0_LV: ICEU2.5(DI) ICEU4.3(A2)
SWO: ICEJ4.6 ICEU1.26(PA.4)
TICECLK: ICEJ4.5 ICEU1.9(PA.10) J1.6 JP4.2 R14.2 U1.66(PF.1/ICE_CLK)
TICEDAT: ICEJ4.3 ICEU1.10(PA.9) J1.4 JP4.1 R13.2 U1.65(PF.0/ICE_DAT)
TICERST: C9.2 ICEJ4.7 ICEU1.14(PF.5) J1.8 JP5.32 NU1.3(MCU_RESET) NU5.5(RESET) R3.2 SW1.2 U1.64(nRESET)
USB_D+: JP4.31 R11.1 U1.95(USB_D+)
USB_D-: JP4.30 R9.1 U1.94(USB_D-)
USB_HS_CAP: ICEC2.1 ICEU1.47(HSUSB_VDD12_CAP)
USB_HS_D+: ICER7.1 ICEU1.46(HSUSB_D+)
USB_HS_D-: ICER6.1 ICEU1.44(HSUSB_D-)
USB_HS_REXT: ICER1.1 ICEU1.41(HSUSB_VRES)
USB_HS_VBUS: ICED1.1 ICED3.2 ICEJ2.1 ICEJ3.1(VBUS) ICEU1.43(HSUSB_VBUS)
USB_VBUS: C10.1 CT1.1 D1.1 HJ2.1(VBUS) J2.1(VBUS) J3.1 JP4.29 U1.93(USB_VBUS)
USB_VDD33_CAP: C6.2 JP4.32 U1.96(USB_VDD33_CAP)
VREF: C14.1 C15.2 JP6.25 L5.2 NU4.8(VREF) U1.121(VREF) VREF1.2
N16825237: LEDG1.1 R6.2
N16825240: LEDR1.1 R7.2
N16840819: ICEC6.1 ICEU1.24(LDO_CAP)
N16840960: ICEC3.1 ICEU1.50(LDO_CAP)
N17019924: ICER8.2 ICER9.2 ICEUP2.1(ADJ)
N17029977: ICERP1.8(R4) ICES3.1
N17029979: ICERP1.6(R3) ICES2.1
N17030004: ICERP1.4(R2) ICES1.1
N17030010: ICERP1.2(R1) ICES0.1
N17042369: ICEJ3.6(Shield) ICEJ3.7(Shield) ICEJ3.8(Shield) ICEJ3.9(Shield) ICEJ3.10(Shield) ICEJ3.11(Shield) ICEL2.2
N17110356: HJ2.6(Shield) HJ2.7(Shield) HJ2.8(Shield) HJ2.9(Shield) HJ2.10(Shield) HJ2.11(Shield) J2.6(Shield) J2.7(Shield) J2.8(Shield) J2.9(Shield) J2.10(Shield) J2.11(Shield) L3.2
N17125028: R12.2 SW2.1(A1)
N17155328: ICER18.1 ICEU2.7(HOLD#)
N17155343: ICER19.1 ICEU2.3(WP#)
N17159369: C8.2 R5.1 X1.1
N17159371: C2.2 R2.1 X1.2
N17159463: C1.2 R1.1 X2.1
N17159465: C7.2 R4.1 X2.2
N17167442: D2.1 UP2.2(OUT) UP2.4(OUT)

Not connected (* = marked no-connect by the designer): H1 1; H2 1; H3 1; H4 1; HJ2 4(ID)*; ICEJ3 4(ID)*; ICESW2 3(A3)* 6(B3)*; ICEU1 1(PB.6)* 2(PB.5)* 3(PB.4)* 4(PB.3)* 5(PB.2)* 8(PA.11)* 11(PA.8)* 20(PA.7)* 21(PA.6)* 25(PA.5)* 48(HSUSB_ID)* 60(PB.11)* 61(PB.10)* 64(PB.7)*; ICEU3 3(A2)* 6(B2)*; J1 1* 3* 5*; J2 4(ID)*; J3 4*; NU1 1(NC)*

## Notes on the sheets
sheet 1
- Off-page Connector
- DEBUG
- RESET
- SPI FLASH
- Nu-Trace,   ID0 = 1, ID1 = 1
  Nu-Link2,   ID0 = 0, ID1 = 1
  Nu-LInk2-Me, ID0 = 0, ID1 = 0
- NULINK ID
- KEY
- Power Switch
- VCOM SWITCH
- 12M Crystal
- USB 2.0 HIGH SPEED DEVICES
- LED
- ICE INTERFACE
sheet 2
- P1 - P32
- P65 - P96
- P33 - P64
- P97 - P128
- Mounting Hole
- ICE
- Bypass Cap
- RESET
- HXT & LXT Crystal
- LED
- USB Device
- Power
sheet 3
- P1 - P32
- P65 - P96
- P33 - P64
- P97 - P128
- UNO Interface
- External Connector
